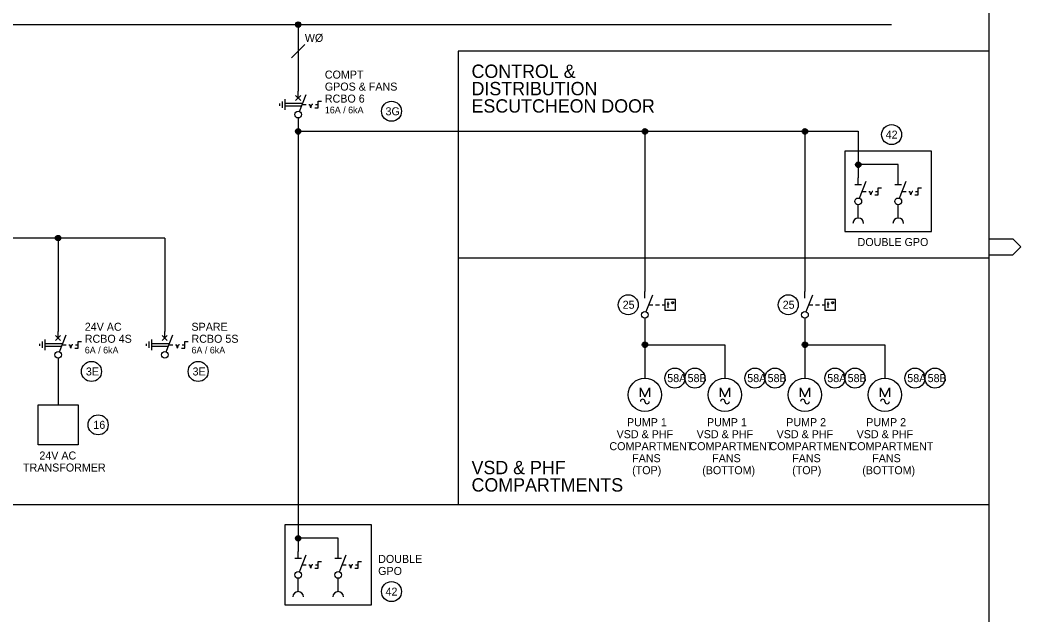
# Model space of a CAD drawing. Extents: x 0 to 841, y 0 to 594.
# Drawn here: x 465.7 to 841, y 158.8 to 381.7 of the extents above; entities that cross this region are included whole.
import ezdxf

# ---------------------------------------------------------------- set-up
doc = ezdxf.new("R2010")
doc.units = 0
for name, color, linetype in [('A1BORDER', 7, 'Continuous'), ('Level 1', 7, 'Continuous'), ('Level 10', 7, 'Continuous')]:
    doc.layers.add(name, color=color, linetype=linetype)

msp = doc.modelspace()

# ---------------------------------------------------------------- linework, layer by layer
at = {"layer": 'A1BORDER'}
for p, q in [((829, 581), (829, 15)), ((829, 299.76), (838, 299.76)), ((838, 299.76), (841, 296.76)), ((838, 293.76), (841, 296.76)), ((829, 293.76), (838, 293.76))]:
    msp.add_line(p, q, dxfattribs=at)
at = {"layer": 'Level 1'}
for p, q in [((60, 380), (792.5, 380)), ((570, 380), (570, 355)), ((567.5, 367.5), (572.5, 372.5)), ((630, 370), (630, 200)), ((829, 370), (630, 370)), ((569.06, 353.44), (570.94, 351.56)), ((570.94, 353.44), (569.06, 351.56)), ((570, 352.5), (570, 355)), ((570.46, 347.41), (573, 353.75)), ((565, 350.5), (571.69795, 350.5)), ((565, 349.5), (571.29732, 349.5)), ((570, 345), (570, 182.5)), ((570, 340), (780, 340)), ((700, 340), (700, 280)), ((760, 340), (760, 280)), ((780, 340), (780, 322.5)), ((795, 327.5), (780, 327.5)), ((795, 322.5), (795, 327.5)), ((778.75, 320), (781.25, 320)), ((780, 320), (780, 322.5)), ((780.46, 314.91), (783, 321.25)), ((793.75, 320), (796.25, 320)), ((795, 320), (795, 322.5)), ((795.46, 314.91), (798, 321.25)), ((780, 307.5), (780, 312.5)), ((795, 307.5), (795, 312.5)), ((520, 300), (360, 300)), ((480, 300), (480, 265)), ((520, 300), (520, 265)), ((829, 292.5), (630, 292.5)), ((700, 277.5), (700, 280)), ((700.46, 272.41), (703, 278.75)), ((760, 277.5), (760, 280)), ((760.46, 272.41), (763, 278.75)), ((701.5, 275), (703, 275)), ((704, 275), (705.5, 275)), ((706.5, 275), (707.5, 275)), ((761.5, 275), (763, 275)), ((764, 275), (765.5, 275)), ((766.5, 275), (767.5, 275)), ((700, 270), (700, 247.5)), ((760, 270), (760, 247.5)), ((479.06, 263.44), (480.94, 261.56)), ((480.94, 263.44), (479.06, 261.56)), ((480, 262.5), (480, 265)), ((480.46, 257.41), (483, 263.75)), ((519.06, 263.44), (520.94, 261.56)), ((520.94, 263.44), (519.06, 261.56)), ((520, 262.5), (520, 265)), ((520.46, 257.41), (523, 263.75)), ((475, 260.5), (481.69795, 260.5)), ((475, 259.5), (481.29732, 259.5)), ((515, 260.5), (521.69795, 260.5)), ((515, 259.5), (521.29732, 259.5)), ((700, 260), (730, 260)), ((730, 260), (730, 247.5)), ((760, 260), (790, 260)), ((790, 260), (790, 247.5)), ((480, 255), (480, 237.5)), ((829, 200), (28, 200)), ((585, 187.5), (570, 187.5)), ((585, 182.5), (585, 187.5)), ((570, 180), (570, 182.5)), ((570.46, 174.91), (573, 181.25)), ((585, 180), (585, 182.5)), ((585.46, 174.91), (588, 181.25)), ((568.75, 180), (571.25, 180)), ((583.75, 180), (586.25, 180)), ((570, 167.5), (570, 172.5)), ((585, 167.5), (585, 172.5))]:
    msp.add_line(p, q, dxfattribs=at)
for points in [[(775, 302.5), (807.5, 302.5), (807.5, 332.5), (775, 332.5)], [(707.5, 273), (711.5, 273), (711.5, 277), (707.5, 277)], [(767.5, 273), (771.5, 273), (771.5, 277), (767.5, 277)], [(472.5, 237.5), (487.5, 237.5), (487.5, 222.5), (472.5, 222.5)], [(565, 162.5), (597.5, 162.5), (597.5, 192.5), (565, 192.5)]]:
    msp.add_lwpolyline(points, close=True, dxfattribs=at)
for points in [[(708.38, 275.38), (709.13, 275.38)], [(708.63, 276.13), (708.63, 273.87)], [(710.36, 275.38), (710.18, 275.42), (710.05, 275.56), (709.99, 275.76), (710.05, 275.94), (710.18, 276.07), (710.36, 276.13), (710.56, 276.07), (710.7, 275.94), (710.74, 275.76), (710.7, 275.56), (710.56, 275.42), (710.36, 275.38)], [(768.38, 275.38), (769.13, 275.38)], [(768.63, 276.13), (768.63, 273.87)], [(770.36, 275.38), (770.18, 275.42), (770.05, 275.56), (769.99, 275.76), (770.05, 275.94), (770.18, 276.07), (770.36, 276.13), (770.56, 276.07), (770.7, 275.94), (770.74, 275.76), (770.7, 275.56), (770.56, 275.42), (770.36, 275.38)]]:
    msp.add_lwpolyline(points, dxfattribs=at)
for centre, radius in [((605, 347.5), 3.75), ((570, 346.25), 1.25), ((792.5, 338.75), 3.75), ((780, 313.75), 1.25), ((795, 313.75), 1.25), ((693.75, 275), 3.75), ((753.75, 275), 3.75), ((700, 271.25), 1.25), ((760, 271.25), 1.25), ((480, 256.25), 1.25), ((520, 256.25), 1.25), ((492.5, 250), 3.75), ((532.5, 250), 3.75), ((711.25, 247.5), 3.75), ((718.75, 247.5), 3.75), ((741.25, 247.5), 3.75), ((748.75, 247.5), 3.75), ((771.25, 247.5), 3.75), ((778.75, 247.5), 3.75), ((801.25, 247.5), 3.75), ((808.75, 247.5), 3.75), ((495, 230), 3.75), ((570, 173.75), 1.25), ((585, 173.75), 1.25), ((605, 167.5), 3.75)]:
    msp.add_circle(centre, radius, dxfattribs=at)
at = {"layer": 'Level 10'}
for p, q in [((569.01, 380.1), (570.99, 380.1)), ((569.02, 379.8), (570.98, 379.8)), ((569.08, 380.4), (570.92, 380.4)), ((569.13, 379.5), (570.87, 379.5)), ((569.29, 380.7), (570.71, 380.7)), ((569.4, 379.2), (570.6, 379.2)), ((570, 381), (570, 381)), ((563, 350.4), (563, 349.6)), ((564, 351.2), (564, 348.8)), ((565, 352), (565, 348)), ((571.5, 350), (573, 350)), ((574, 350), (574.33, 350)), ((574.75, 348.75), (574.33, 350)), ((574.75, 348.75), (575.17, 350)), ((575.5, 350), (575.17, 350)), ((576.5, 350), (577.5, 350)), ((577.5, 348.75), (577.5, 351.25)), ((577.5, 351.25), (578.75, 351.25)), ((576.25, 348.75), (577.5, 348.75)), ((569, 340), (570.99, 340)), ((569.05, 340.3), (570.95, 340.3)), ((569.05, 339.7), (570.95, 339.7)), ((569.2, 340.6), (570.8, 340.6)), ((569.2, 339.4), (570.8, 339.4)), ((569.56, 340.9), (570.44, 340.9)), ((569.56, 339.1), (570.44, 339.1)), ((570, 341), (570, 341)), ((699, 340), (700.99, 340)), ((699.05, 340.3), (700.95, 340.3)), ((699.05, 339.7), (700.95, 339.7)), ((699.2, 340.6), (700.8, 340.6)), ((699.2, 339.4), (700.8, 339.4)), ((699.56, 340.9), (700.44, 340.9)), ((699.56, 339.1), (700.44, 339.1)), ((700, 341), (700, 341)), ((759, 340), (760.99, 340)), ((759.05, 340.3), (760.95, 340.3)), ((759.05, 339.7), (760.95, 339.7)), ((759.2, 340.6), (760.8, 340.6)), ((759.2, 339.4), (760.8, 339.4)), ((759.56, 340.9), (760.44, 340.9)), ((759.56, 339.1), (760.44, 339.1)), ((760, 341), (760, 341)), ((779, 327.5), (780.99, 327.5)), ((779.05, 327.8), (780.95, 327.8)), ((779.05, 327.2), (780.95, 327.2)), ((779.2, 328.1), (780.8, 328.1)), ((779.2, 326.9), (780.8, 326.9)), ((779.56, 328.4), (780.44, 328.4)), ((779.56, 326.6), (780.44, 326.6)), ((780, 328.5), (780, 328.5)), ((781.5, 317.5), (783, 317.5)), ((784, 317.5), (784.33, 317.5)), ((784.75, 316.25), (784.33, 317.5)), ((784.75, 316.25), (785.17, 317.5)), ((785.5, 317.5), (785.17, 317.5)), ((786.25, 316.25), (787.5, 316.25)), ((786.5, 317.5), (787.5, 317.5)), ((787.5, 316.25), (787.5, 318.75)), ((787.5, 318.75), (788.75, 318.75)), ((796.5, 317.5), (798, 317.5)), ((799, 317.5), (799.33, 317.5)), ((799.75, 316.25), (799.33, 317.5)), ((799.75, 316.25), (800.17, 317.5)), ((800.5, 317.5), (800.17, 317.5)), ((801.25, 316.25), (802.5, 316.25)), ((801.5, 317.5), (802.5, 317.5)), ((802.5, 316.25), (802.5, 318.75)), ((802.5, 318.75), (803.75, 318.75)), ((479.08, 300.4), (480.92, 300.4)), ((479.29, 300.7), (480.71, 300.7)), ((480, 301), (480, 301)), ((479.01, 300.1), (480.99, 300.1)), ((479.02, 299.8), (480.98, 299.8)), ((479.13, 299.5), (480.87, 299.5)), ((479.4, 299.2), (480.6, 299.2)), ((473, 260.4), (473, 259.6)), ((474, 261.2), (474, 258.8)), ((475, 262), (475, 258)), ((481.5, 260), (483, 260)), ((484, 260), (484.33, 260)), ((484.75, 258.75), (484.33, 260)), ((484.75, 258.75), (485.17, 260)), ((485.5, 260), (485.17, 260)), ((486.5, 260), (487.5, 260)), ((487.5, 258.75), (487.5, 261.25)), ((487.5, 261.25), (488.75, 261.25)), ((513, 260.4), (513, 259.6)), ((514, 261.2), (514, 258.8)), ((515, 262), (515, 258)), ((521.5, 260), (523, 260)), ((524, 260), (524.33, 260)), ((524.75, 258.75), (524.33, 260)), ((524.75, 258.75), (525.17, 260)), ((525.5, 260), (525.17, 260)), ((526.5, 260), (527.5, 260)), ((527.5, 258.75), (527.5, 261.25)), ((527.5, 261.25), (528.75, 261.25)), ((699, 260), (700.99, 260)), ((699.05, 260.3), (700.95, 260.3)), ((699.05, 259.7), (700.95, 259.7)), ((699.2, 260.6), (700.8, 260.6)), ((699.2, 259.4), (700.8, 259.4)), ((699.56, 260.9), (700.44, 260.9)), ((699.56, 259.1), (700.44, 259.1)), ((700, 261), (700, 261)), ((759, 260), (760.99, 260)), ((759.05, 260.3), (760.95, 260.3)), ((759.05, 259.7), (760.95, 259.7)), ((759.2, 260.6), (760.8, 260.6)), ((759.2, 259.4), (760.8, 259.4)), ((759.56, 260.9), (760.44, 260.9)), ((759.56, 259.1), (760.44, 259.1)), ((760, 261), (760, 261)), ((486.25, 258.75), (487.5, 258.75)), ((526.25, 258.75), (527.5, 258.75)), ((698.33, 243.83), (700, 240.5)), ((698.33, 240.5), (698.33, 243.83)), ((700, 240.5), (701.67, 243.83)), ((701.67, 243.83), (701.67, 240.5)), ((728.33, 243.83), (730, 240.5)), ((728.33, 240.5), (728.33, 243.83)), ((730, 240.5), (731.67, 243.83)), ((731.67, 243.83), (731.67, 240.5)), ((758.33, 243.83), (760, 240.5)), ((758.33, 240.5), (758.33, 243.83)), ((760, 240.5), (761.67, 243.83)), ((761.67, 243.83), (761.67, 240.5)), ((788.33, 243.83), (790, 240.5)), ((788.33, 240.5), (788.33, 243.83)), ((790, 240.5), (791.67, 243.83)), ((791.67, 243.83), (791.67, 240.5)), ((569.05, 187.8), (570.95, 187.8)), ((569.2, 188.1), (570.8, 188.1)), ((569.56, 188.4), (570.44, 188.4)), ((570, 188.5), (570, 188.5)), ((569, 187.5), (570.99, 187.5)), ((569.05, 187.2), (570.95, 187.2)), ((569.2, 186.9), (570.8, 186.9)), ((569.56, 186.6), (570.44, 186.6)), ((571.5, 177.5), (573, 177.5)), ((574, 177.5), (574.33, 177.5)), ((574.75, 176.25), (574.33, 177.5)), ((574.75, 176.25), (575.17, 177.5)), ((575.5, 177.5), (575.17, 177.5)), ((576.5, 177.5), (577.5, 177.5)), ((577.5, 176.25), (577.5, 178.75)), ((577.5, 178.75), (578.75, 178.75)), ((586.5, 177.5), (588, 177.5)), ((589, 177.5), (589.33, 177.5)), ((589.75, 176.25), (589.33, 177.5)), ((589.75, 176.25), (590.17, 177.5)), ((590.5, 177.5), (590.17, 177.5)), ((591.5, 177.5), (592.5, 177.5)), ((592.5, 176.25), (592.5, 178.75)), ((592.5, 178.75), (593.75, 178.75)), ((576.25, 176.25), (577.5, 176.25)), ((591.25, 176.25), (592.5, 176.25))]:
    msp.add_line(p, q, dxfattribs=at)
for centre, radius in [((570, 380), 1), ((570, 340), 1), ((700, 340), 1), ((760, 340), 1), ((780, 327.5), 1), ((480, 300), 1), ((700, 260), 1), ((760, 260), 1), ((700, 241.25), 6.25), ((730, 241.25), 6.25), ((760, 241.25), 6.25), ((790, 241.25), 6.25), ((570, 187.5), 1)]:
    msp.add_circle(centre, radius, dxfattribs=at)
for centre, radius, start, end in [((780, 305.5), 2, 0, 180), ((795, 305.5), 2, 0, 180), ((699.17, 238.75), 0.83, 0, 180), ((700.83, 238.75), 0.83, 180, 0), ((729.17, 238.75), 0.83, 0, 180), ((730.83, 238.75), 0.83, 180, 0), ((759.17, 238.75), 0.83, 0, 180), ((760.83, 238.75), 0.83, 180, 0), ((789.17, 238.75), 0.83, 0, 180), ((790.83, 238.75), 0.83, 180, 0), ((570, 165.5), 2, 0, 180), ((585, 165.5), 2, 0, 180)]:
    msp.add_arc(centre, radius, start, end, dxfattribs=at)

# ---------------------------------------------------------------- texts
at = {"layer": 'Level 1'}
for s, height, p in [('W%%C', 3, (572.5, 373.5)), ('CONTROL &', 5, (635, 360)), ('COMPT', 3, (580, 359.75)), ('GPOS & FANS', 3, (580, 355.25)), ('DISTRIBUTION', 5, (635, 353.5)), ('RCBO 6', 3, (580, 350.75)), ('16A / 6kA', 2.50002, (580, 346.75)), ('3G', 3, (602.75879, 346)), ('ESCUTCHEON DOOR', 5, (635, 347)), ('42', 3, (790.25879, 337.25)), ('DOUBLE GPO', 3, (779.74512, 297)), ('25', 3, (691.6582, 273.5)), ('25', 3, (751.6582, 273.5)), ('24V AC', 3, (490, 265.25)), ('SPARE', 3, (530, 265.25)), ('RCBO 4S', 3, (490, 260.75)), ('RCBO 5S', 3, (530, 260.75)), ('6A / 6kA', 2.50002, (490, 256.75)), ('6A / 6kA', 2.50002, (530, 256.75)), ('3E', 3, (490.4082, 248.5)), ('3E', 3, (530.4082, 248.5)), ('58A', 3, (708.38623, 246)), ('58B', 3, (716.01074, 246)), ('58A', 3, (738.38623, 246)), ('58B', 3, (746.01074, 246)), ('58A', 3, (768.38623, 246)), ('58B', 3, (776.01074, 246)), ('58A', 3, (798.38623, 246)), ('58B', 3, (806.01074, 246)), ('16', 3, (493.20703, 228.5)), ('PUMP 1', 3, (693.27637, 229.5)), ('PUMP 1', 3, (723.27637, 229.5)), ('PUMP 2', 3, (752.97754, 229.5)), ('PUMP 2', 3, (782.97754, 229.5)), ('VSD & PHF', 3, (689.3916, 225)), ('VSD & PHF', 3, (719.3916, 225)), ('VSD & PHF', 3, (749.3916, 225)), ('VSD & PHF', 3, (779.3916, 225)), ('COMPARTMENT', 3, (686.70215, 220.5)), ('COMPARTMENT', 3, (716.70215, 220.5)), ('COMPARTMENT', 3, (746.70215, 220.5)), ('COMPARTMENT', 3, (776.70215, 220.5)), ('24V AC', 3, (472.97754, 217)), ('FANS', 3, (695.21875, 216)), ('FANS', 3, (725.21875, 216)), ('FANS', 3, (755.21875, 216)), ('FANS', 3, (785.21875, 216)), ('TRANSFORMER', 3, (466.85156, 212.5)), ('VSD & PHF', 5, (635, 211.5)), ('(TOP)', 3, (695.21875, 211.5)), ('(BOTTOM)', 3, (721.4834, 211.5)), ('(TOP)', 3, (755.21875, 211.5)), ('(BOTTOM)', 3, (781.4834, 211.5)), ('COMPARTMENTS', 5, (635, 205)), ('DOUBLE', 3, (600, 178.25)), ('GPO', 3, (600, 173.75)), ('42', 3, (602.75879, 166))]:
    msp.add_text(s, height=height, dxfattribs=at).set_placement(p)

doc.saveas('drawing.dxf')
